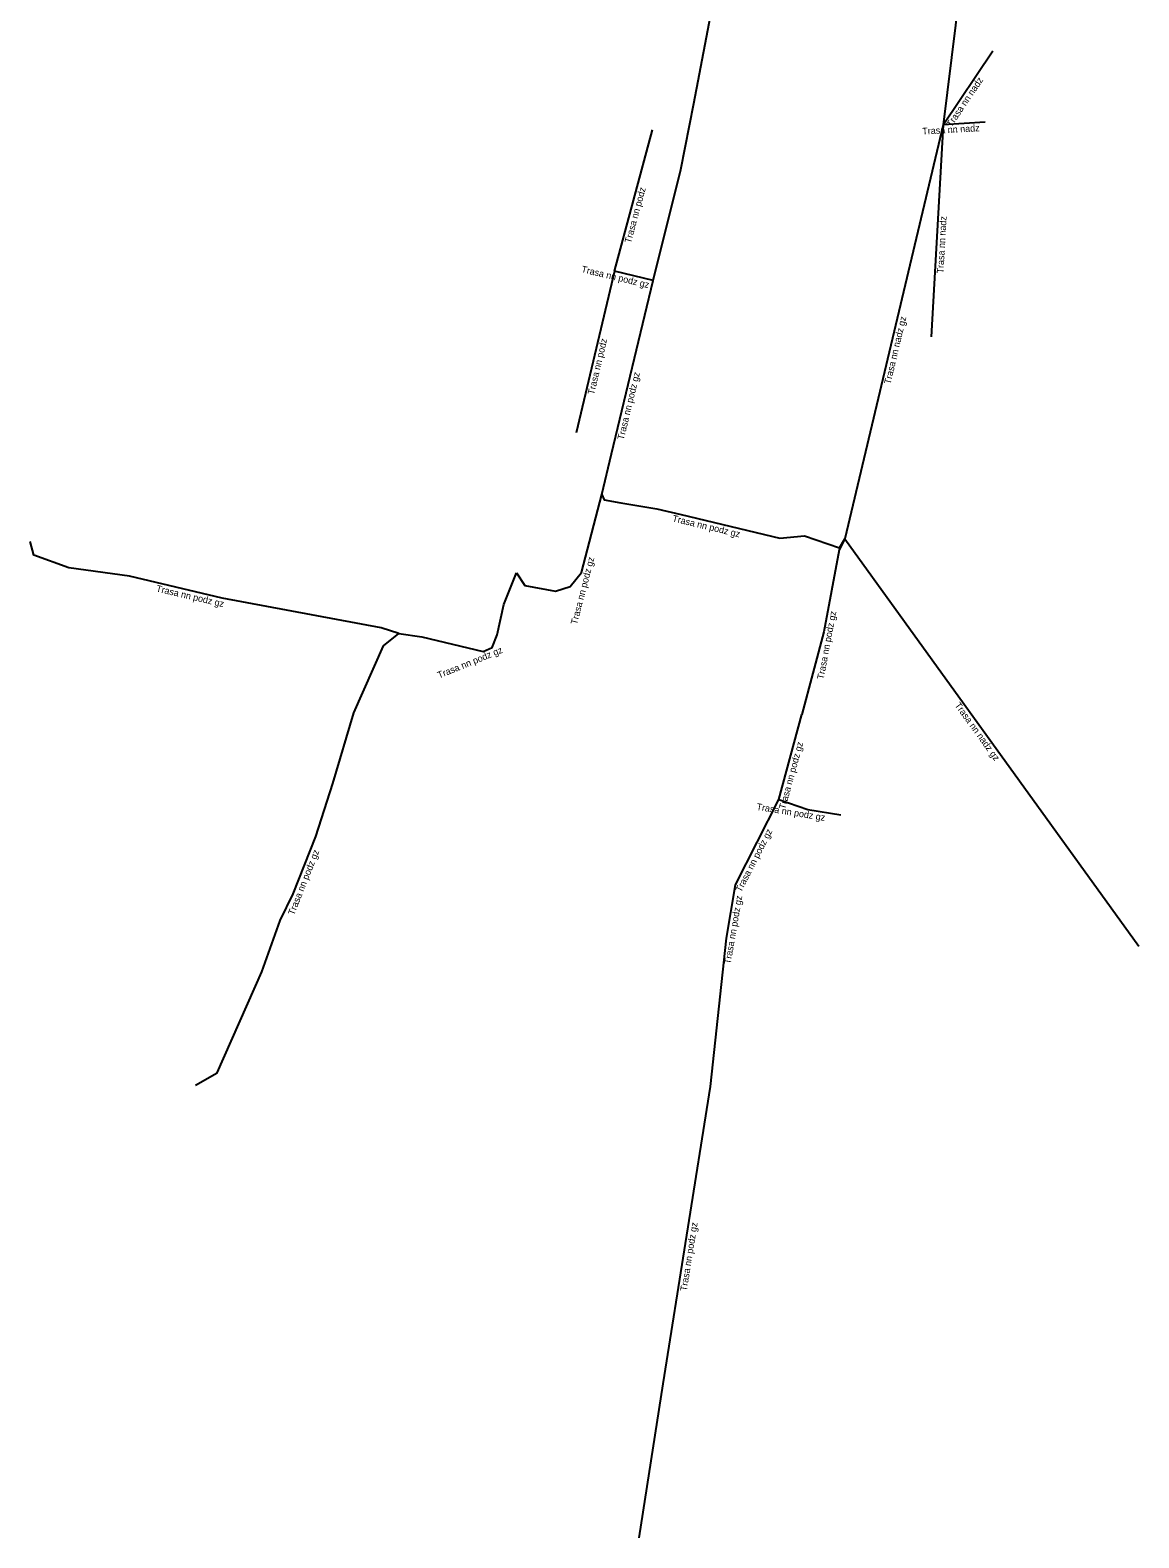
# Model space of a CAD drawing. Extents: x -492667 to -492262, y -1127463 to -1126980.
# Drawn here: x -492563 to -492480.4, y -1127462.8 to -1127350.5 of the extents above; entities that cross this region are included whole.
import ezdxf

# ---------------------------------------------------------------- set-up
doc = ezdxf.new("R2010")
doc.units = 0
doc.layers.add('Popiskový text - Ostatní atributy Trasy', color=7, linetype='Continuous')
doc.layers.add('Spojnice NN', color=7, linetype='Continuous')

msp = doc.modelspace()

# ---------------------------------------------------------------- linework, layer by layer
at = {"layer": 'Spojnice NN'}
for points in [[(-492516.59, -1127369.15), (-492514.53, -1127360.89), (-492513.57, -1127355.97), (-492512.09, -1127348.29), (-492510.7, -1127340.9), (-492510.17, -1127336.39), (-492511.11, -1127323.63), (-492512.39, -1127318.08), (-492512.81, -1127315.15), (-492513.17, -1127314.78), (-492513.82, -1127314.76), (-492514.52, -1127315.02)], [(-492491.31, -1127327.66), (-492495.01, -1127357.55)], [(-492495.01, -1127357.55), (-492491.31, -1127352.05)], [(-492519.48, -1127368.46), (-492516.63, -1127357.94)], [(-492495.01, -1127357.55), (-492502.31, -1127388.4)], [(-492495.01, -1127357.55), (-492495.9, -1127373.36)], [(-492491.86, -1127357.36), (-492495.01, -1127357.55)], [(-492519.48, -1127368.46), (-492522.32, -1127380.49)], [(-492520.42, -1127385.1), (-492519.69, -1127382.05), (-492516.59, -1127369.15)], [(-492516.59, -1127369.15), (-492519.48, -1127368.46)], [(-492526.77, -1127390.93), (-492526.14, -1127391.87), (-492523.86, -1127392.28), (-492522.76, -1127391.94), (-492521.92, -1127390.89), (-492520.42, -1127385.1)], [(-492520.42, -1127385.1), (-492520.25, -1127385.48), (-492519, -1127385.72), (-492516.33, -1127386.16), (-492514.5, -1127386.59), (-492507.15, -1127388.34), (-492505.33, -1127388.18), (-492502.72, -1127389.06), (-492502.31, -1127388.4)], [(-492502.31, -1127388.4), (-492502.75, -1127389.22), (-492503.89, -1127395.31), (-492505.51, -1127401.48)], [(-492502.31, -1127388.4), (-492480.43, -1127418.73)], [(-492535.53, -1127395.44), (-492536.85, -1127395.02), (-492548.69, -1127392.8), (-492555.58, -1127391.18), (-492560.09, -1127390.55), (-492562.71, -1127389.62), (-492562.98, -1127388.58)], [(-492535.53, -1127395.44), (-492533.81, -1127395.7), (-492529.26, -1127396.77), (-492528.58, -1127396.49), (-492528.21, -1127395.54), (-492527.7, -1127393.28), (-492526.77, -1127390.93)], [(-492550.67, -1127429.07), (-492549.05, -1127428.16), (-492545.74, -1127420.63), (-492544.36, -1127416.81), (-492543.39, -1127414.83), (-492541.7, -1127410.55), (-492540.44, -1127406.61), (-492538.87, -1127401.34), (-492536.67, -1127396.36), (-492535.53, -1127395.44)], [(-492507.23, -1127407.81), (-492505.51, -1127401.48)], [(-492510.46, -1127414.16), (-492507.23, -1127407.81)], [(-492507.23, -1127407.81), (-492505.07, -1127408.54), (-492502.63, -1127408.94)], [(-492511.14, -1127418.13), (-492510.46, -1127414.16)], [(-492517.63, -1127462.79), (-492515.84, -1127451.32), (-492512.33, -1127429.18), (-492511.14, -1127418.13)]]:
    msp.add_lwpolyline(points, dxfattribs=at)

# ---------------------------------------------------------------- texts
at = {"layer": 'Popiskový text - Ostatní atributy Trasy'}
for s, rotation, p in [('Trasa nn nadz', 56.0571, (-492494.38, -1127357.77)), ('Trasa nn nadz', 3.3976, (-492496.54, -1127358.29)), ('Trasa nn podz', 74.8417, (-492518.25, -1127366.41)), ('Trasa nn nadz', 86.7853, (-492494.98, -1127368.64)), ('Trasa nn podz gz', 346.5825, (-492521.97, -1127368.53)), ('Trasa nn nadz gz', 76.687, (-492498.92, -1127376.91)), ('Trasa nn podz', 76.7289, (-492520.99, -1127377.69)), ('Trasa nn podz gz', 76.4989, (-492518.78, -1127381.06)), ('Trasa nn podz gz', 346.565, (-492515.2, -1127387.09)), ('Trasa nn podz gz', 75.4659, (-492522.26, -1127394.81)), ('Trasa nn podz gz', 346.8105, (-492553.63, -1127392.31)), ('Trasa nn podz gz', 79.3829, (-492503.9, -1127398.89)), ('Trasa nn podz gz', 22.1343, (-492532.53, -1127398.8)), ('Trasa nn nadz gz', 305.8053, (-492494.17, -1127400.79)), ('Trasa nn podz gz', 74.8705, (-492506.76, -1127408.57)), ('Trasa nn podz gz', 350.7321, (-492508.92, -1127408.57)), ('Trasa nn podz gz', 62.9674, (-492510.04, -1127414.75)), ('Trasa nn podz gz', 68.4645, (-492543.33, -1127416.46)), ('Trasa nn podz gz', 80.3016, (-492510.82, -1127420.09)), ('Trasa nn podz gz', 80.9718, (-492514.09, -1127444.44))]:
    msp.add_text(s, height=0.5, rotation=rotation, dxfattribs=at).set_placement(p)

doc.saveas('drawing.dxf')
